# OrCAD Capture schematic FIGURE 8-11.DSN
size A
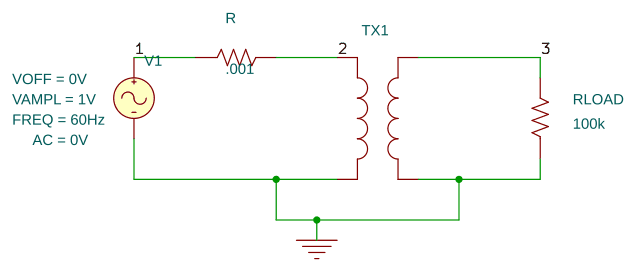
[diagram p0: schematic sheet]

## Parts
R  .001  [AX/RC05]
RLOAD  100k  [AX/RC05]
TX1  XFRM_LINEAR
V1  VSIN

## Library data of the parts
R RLOAD = R
TX1 = XFRM_LINEAR
V1 = VSIN: AC: 0V; FREQ: 60Hz; VAMPL: 1V; VOFF: 0V

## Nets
0: RLOAD.1 TX1.2 TX1.4 V1.2(-)
1: R.1 V1.1(+)
2: R.2 TX1.1
3: RLOAD.2 TX1.3
